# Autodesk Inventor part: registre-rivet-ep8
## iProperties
Author: chr
Created: 2001-06
Part Number: registre-rivet-ep8
Material: Par défaut
Document SubType Name: Modélisation
Designer: chr
Control State: 0
Master: False
Checked Out: False
PropertySet Name: Design Tracking Control
Shininess: 20.0
PropertySet Name: _Private Model Information
Length Units: 11269
Angle Units: 11286
Time Units: 11279
Mass Units: 11290
Length Display Precision: 3
Angle Display Precision: 2
Compacted: False
Density: 0.0
Volumn: 0.0
Area: 0.0
PropertySet Name: Model Information
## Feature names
1. Révolution1 [Revolution]
2. Symétrie1 [Mirror]
